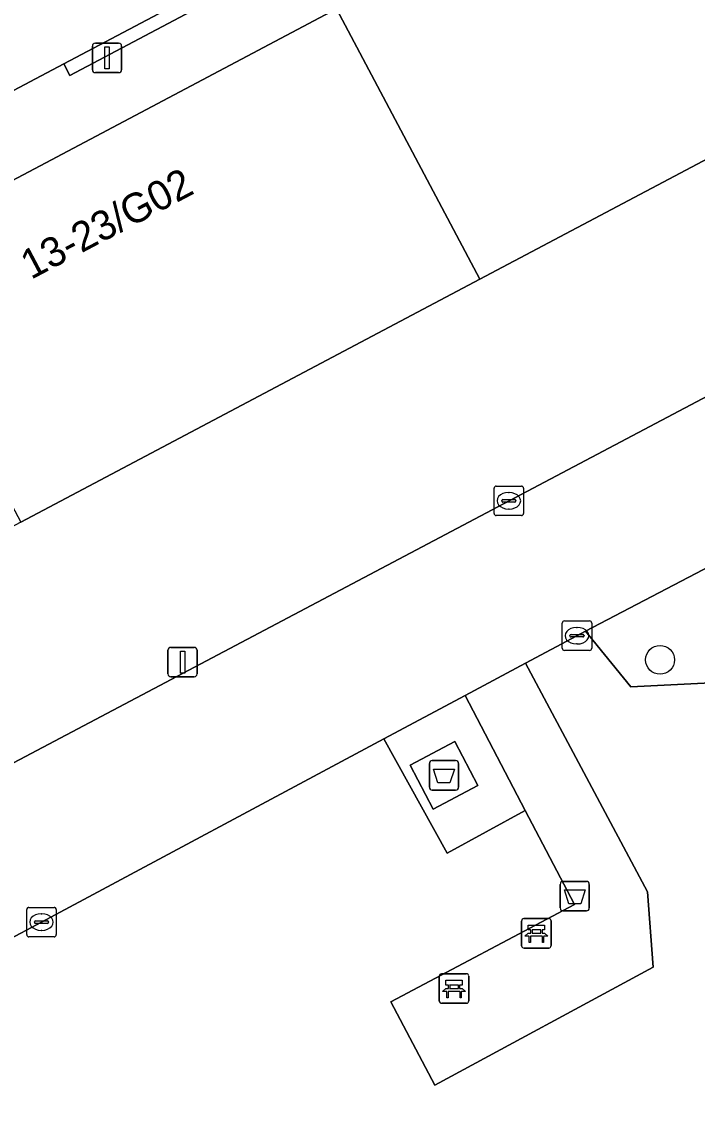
# Model space of a CAD drawing. Extents: x 159674 to 160531, y 382172 to 382904.
# Drawn here: x 160052.01 to 160074.9, y 382265.94 to 382302.84 of the extents above; entities that cross this region are included whole.
import ezdxf

# ---------------------------------------------------------------- set-up
doc = ezdxf.new("R2010")
doc.units = 0
for name, color, linetype in [('IMGEO_Afval_apart_plaats', 7, 'Continuous'), ('IMGEO_Afvalbak', 7, 'Continuous'), ('IMGEO_Bank', 7, 'Continuous'), ('IMGEO_Boom', 7, 'Continuous'), ('IMGEO_Erf', 7, 'Continuous'), ('IMGEO_Groenvoorziening', 7, 'Continuous'), ('IMGEO_Kolk', 7, 'Continuous'), ('IMGEO_Lichtmast', 7, 'Continuous'), ('IMGEO_Pand', 7, 'Continuous'), ('IMGEO_Pand_nummerreeks', 7, 'Continuous'), ('IMGEO_Rijbaan_lokaal_open', 7, 'Continuous'), ('IMGEO_Voetpad_gesloten', 7, 'Continuous'), ('IMGEO_Voetpad_open', 7, 'Continuous')]:
    doc.layers.add(name, color=color, linetype=linetype)

msp = doc.modelspace()

# ---------------------------------------------------------------- linework, layer by layer
at = {"layer": 'IMGEO_Afval_apart_plaats'}
for p, q in [((160065.925, 382277.79), (160066.715, 382277.79)), ((160066.715, 382277.79), (160065.925, 382277.79)), ((160065.825, 382276.89), (160065.825, 382277.69)), ((160065.825, 382277.69), (160065.825, 382276.89)), ((160066.815, 382277.69), (160066.815, 382276.89)), ((160066.815, 382276.89), (160066.815, 382277.69)), ((160066.715, 382276.79), (160065.925, 382276.79)), ((160065.925, 382276.79), (160066.715, 382276.79))]:
    msp.add_line(p, q, dxfattribs=at)
msp.add_lwpolyline([(160065.968, 382277.504), (160066.672, 382277.504), (160066.523, 382277.034), (160066.117, 382277.034), (160065.968, 382277.504)], dxfattribs=at)
for centre, start, end in [((160065.925, 382277.69), 90, 180), ((160065.925, 382277.69), 90, 180), ((160066.715, 382277.69), 0, 90), ((160066.715, 382277.69), 360, 90), ((160065.925, 382276.89), 180, 270), ((160065.925, 382276.89), 180, 270), ((160066.715, 382276.89), 270, 0), ((160066.715, 382276.89), 270, 0)]:
    msp.add_arc(centre, 0.1, start, end, dxfattribs=at)
at = {"layer": 'IMGEO_Afvalbak'}
for p, q in [((160070.357, 382273.695), (160071.147, 382273.695)), ((160071.147, 382273.695), (160070.357, 382273.695)), ((160070.257, 382272.795), (160070.257, 382273.595)), ((160070.257, 382273.595), (160070.257, 382272.795)), ((160071.247, 382273.595), (160071.247, 382272.795)), ((160071.247, 382272.795), (160071.247, 382273.595)), ((160071.147, 382272.695), (160070.357, 382272.695)), ((160070.357, 382272.695), (160071.147, 382272.695))]:
    msp.add_line(p, q, dxfattribs=at)
msp.add_lwpolyline([(160070.4, 382273.409), (160071.104, 382273.409), (160070.955, 382272.939), (160070.549, 382272.939), (160070.4, 382273.409)], dxfattribs=at)
for centre, start, end in [((160070.357, 382273.595), 90, 180), ((160070.357, 382273.595), 90, 180), ((160071.147, 382273.595), 0, 90), ((160071.147, 382273.595), 360, 90), ((160070.357, 382272.795), 180, 270), ((160070.357, 382272.795), 180, 270), ((160071.147, 382272.795), 270, 0), ((160071.147, 382272.795), 270, 0)]:
    msp.add_arc(centre, 0.1, start, end, dxfattribs=at)
at = {"layer": 'IMGEO_Bank'}
for p, q in [((160068.952, 382271.51), (160068.952, 382272.351)), ((160068.952, 382272.351), (160068.952, 382271.51)), ((160069.027, 382272.435), (160069.868, 382272.435)), ((160069.868, 382272.435), (160069.027, 382272.435)), ((160069.952, 382272.36), (160069.952, 382271.519)), ((160069.952, 382271.519), (160069.952, 382272.36)), ((160069.649, 382271.833), (160069.256, 382271.833)), ((160069.261, 382271.941), (160069.261, 382272.047)), ((160069.305, 382272.047), (160069.305, 382271.941)), ((160069.593, 382272.053), (160069.311, 382272.053)), ((160069.311, 382271.935), (160069.593, 382271.935)), ((160069.599, 382271.941), (160069.599, 382272.047)), ((160069.643, 382272.047), (160069.643, 382271.941)), ((160069.877, 382271.435), (160069.036, 382271.435)), ((160069.036, 382271.435), (160069.877, 382271.435)), ((160066.161, 382269.637), (160066.161, 382270.478)), ((160066.161, 382270.478), (160066.161, 382269.637)), ((160066.236, 382270.562), (160067.077, 382270.562)), ((160067.077, 382270.562), (160066.236, 382270.562)), ((160067.161, 382270.487), (160067.161, 382269.646)), ((160067.161, 382269.646), (160067.161, 382270.487)), ((160066.47, 382270.068), (160066.47, 382270.174)), ((160066.514, 382270.174), (160066.514, 382270.068)), ((160066.802, 382270.18), (160066.52, 382270.18)), ((160066.52, 382270.062), (160066.802, 382270.062)), ((160066.808, 382270.068), (160066.808, 382270.174)), ((160066.852, 382270.174), (160066.852, 382270.068)), ((160066.858, 382269.96), (160066.465, 382269.96)), ((160067.086, 382269.562), (160066.245, 382269.562)), ((160066.245, 382269.562), (160067.086, 382269.562))]:
    msp.add_line(p, q, dxfattribs=at)
for points in [[(160069.255, 382272.053), (160069.169, 382272.053), (160069.169, 382272.214), (160069.732, 382272.214), (160069.732, 382272.053), (160069.649, 382272.053)], [(160069.199, 382271.833), (160069.057, 382271.833), (160069.169, 382271.935), (160069.255, 382271.935)], [(160069.249, 382271.826), (160069.249, 382271.619), (160069.206, 382271.619), (160069.206, 382271.826)], [(160069.649, 382271.935), (160069.732, 382271.935), (160069.844, 382271.833), (160069.705, 382271.833)], [(160069.699, 382271.826), (160069.699, 382271.619), (160069.655, 382271.619), (160069.655, 382271.826)], [(160066.408, 382269.96), (160066.266, 382269.96), (160066.378, 382270.062), (160066.464, 382270.062)], [(160066.464, 382270.18), (160066.378, 382270.18), (160066.378, 382270.341), (160066.941, 382270.341), (160066.941, 382270.18), (160066.858, 382270.18)], [(160066.858, 382270.062), (160066.941, 382270.062), (160067.053, 382269.96), (160066.914, 382269.96)], [(160066.458, 382269.953), (160066.458, 382269.746), (160066.415, 382269.746), (160066.415, 382269.953)], [(160066.908, 382269.953), (160066.908, 382269.746), (160066.864, 382269.746), (160066.864, 382269.953)]]:
    msp.add_lwpolyline(points, dxfattribs=at)
for centre, radius, start, end in [((160069.03, 382272.357), 0.0779, 92.4484, 184.2845), ((160069.03, 382272.357), 0.0779, 92.4484, 184.2845), ((160069.874, 382272.357), 0.0779, 2.4484, 94.2845), ((160069.874, 382272.357), 0.0779, 2.4484, 94.2845), ((160069.199, 382271.826), 0.00671, 2.8957, 87.1043), ((160069.256, 382271.826), 0.00671, 92.8957, 177.1043), ((160069.254, 382272.046), 0.00671, 2.8957, 87.1043), ((160069.254, 382271.942), 0.00671, 272.8957, 357.1043), ((160069.311, 382272.046), 0.00671, 92.8957, 177.1043), ((160069.311, 382271.942), 0.00671, 182.8957, 267.1043), ((160069.593, 382272.046), 0.00671, 2.8957, 87.1043), ((160069.593, 382271.942), 0.00671, 272.8957, 357.1043), ((160069.65, 382272.046), 0.00671, 92.8957, 177.1043), ((160069.65, 382271.942), 0.00671, 182.8957, 267.1043), ((160069.648, 382271.826), 0.00671, 2.8957, 87.1043), ((160069.705, 382271.826), 0.00671, 92.8957, 177.1043), ((160069.03, 382271.513), 0.0779, 182.4484, 274.2845), ((160069.03, 382271.513), 0.0779, 182.4484, 274.2845), ((160069.874, 382271.513), 0.0779, 272.4484, 4.2845), ((160069.874, 382271.513), 0.0779, 272.4484, 4.2845), ((160066.239, 382270.484), 0.0779, 92.4484, 184.2845), ((160066.239, 382270.484), 0.0779, 92.4484, 184.2845), ((160067.083, 382270.484), 0.0779, 2.4484, 94.2845), ((160067.083, 382270.484), 0.0779, 2.4484, 94.2845), ((160066.463, 382270.173), 0.00671, 2.8957, 87.1043), ((160066.463, 382270.069), 0.00671, 272.8957, 357.1043), ((160066.52, 382270.173), 0.00671, 92.8957, 177.1043), ((160066.52, 382270.069), 0.00671, 182.8957, 267.1043), ((160066.802, 382270.173), 0.00671, 2.8957, 87.1043), ((160066.802, 382270.069), 0.00671, 272.8957, 357.1043), ((160066.859, 382270.173), 0.00671, 92.8957, 177.1043), ((160066.859, 382270.069), 0.00671, 182.8957, 267.1043), ((160066.239, 382269.64), 0.0779, 182.4484, 274.2845), ((160066.239, 382269.64), 0.0779, 182.4484, 274.2845), ((160066.408, 382269.953), 0.00671, 2.8957, 87.1043), ((160066.465, 382269.953), 0.00671, 92.8957, 177.1043), ((160066.857, 382269.953), 0.00671, 2.8957, 87.1043), ((160066.914, 382269.953), 0.00671, 92.8957, 177.1043), ((160067.083, 382269.64), 0.0779, 272.4484, 4.2845), ((160067.083, 382269.64), 0.0779, 272.4484, 4.2845)]:
    msp.add_arc(centre, radius, start, end, dxfattribs=at)
at = {"layer": 'IMGEO_Boom'}
msp.add_circle((160073.644, 382281.208), 0.489, dxfattribs=at)
at = {"layer": 'IMGEO_Erf'}
for points in [[(160086.028, 382319.631), (160083.339, 382319.397), (160078.204, 382311.499), (160083.057, 382302.331), (160067.532, 382294.112), (160051.977, 382285.878), (160036.422, 382277.643), (160020.867, 382269.409), (160016.014, 382278.577), (160005.765, 382273.145), (160019.447, 382262.957), (160024.762, 382259.009)], [(160034.319, 382268.512), (160078.039, 382291.633)]]:
    msp.add_lwpolyline(points, dxfattribs=at)
at = {"layer": 'IMGEO_Groenvoorziening'}
for points in [[(160079.096, 382286.347), (160071.119, 382282.18), (160072.654, 382280.295), (160075.37, 382280.425), (160104.517, 382274.01), (160105.327, 382275.04), (160090.303, 382285.839)], [(160067.688, 382235.292), (160105.142, 382241.788), (160106.23, 382250), (160109.176, 382272.273), (160105.327, 382275.04), (160104.517, 382274.01), (160075.37, 382280.425), (160072.654, 382280.295), (160071.119, 382282.18), (160070.827, 382282.027), (160069.084, 382281.094), (160073.22, 382273.339), (160073.408, 382270.787), (160066.015, 382266.781), (160064.524, 382269.606), (160070.744, 382272.909), (160069.073, 382276.104), (160066.433, 382274.656), (160064.282, 382278.525), (160052.678, 382272.316), (160035.422, 382263.138)]]:
    msp.add_lwpolyline(points, dxfattribs=at)
at = {"layer": 'IMGEO_Kolk'}
for p, q in [((160068.018, 382286.174), (160068.018, 382287.026)), ((160068.093, 382287.1), (160068.945, 382287.1)), ((160069.019, 382287.026), (160069.019, 382286.174)), ((160068.277, 382286.594), (160068.277, 382286.606)), ((160068.32, 382286.643), (160068.718, 382286.643)), ((160068.506, 382286.88), (160068.531, 382286.88)), ((160068.761, 382286.606), (160068.761, 382286.594)), ((160068.715, 382286.557), (160068.317, 382286.557)), ((160068.529, 382286.32), (160068.504, 382286.32)), ((160068.945, 382286.1), (160068.093, 382286.1)), ((160070.402, 382282.526), (160071.254, 382282.526)), ((160070.327, 382281.6), (160070.327, 382282.452)), ((160070.815, 382282.306), (160070.84, 382282.306)), ((160071.328, 382282.452), (160071.328, 382281.6)), ((160070.586, 382282.02), (160070.586, 382282.032)), ((160071.024, 382281.983), (160070.626, 382281.983)), ((160070.629, 382282.069), (160071.027, 382282.069)), ((160071.07, 382282.032), (160071.07, 382282.02)), ((160071.254, 382281.526), (160070.402, 382281.526)), ((160070.838, 382281.746), (160070.813, 382281.746)), ((160052.178, 382271.889), (160052.178, 382272.741)), ((160052.253, 382272.815), (160053.105, 382272.815)), ((160052.666, 382272.595), (160052.691, 382272.595)), ((160053.179, 382272.741), (160053.179, 382271.889)), ((160052.437, 382272.309), (160052.437, 382272.321)), ((160052.875, 382272.272), (160052.477, 382272.272)), ((160052.48, 382272.358), (160052.878, 382272.358)), ((160052.921, 382272.321), (160052.921, 382272.309)), ((160052.689, 382272.035), (160052.664, 382272.035)), ((160053.105, 382271.815), (160052.253, 382271.815))]:
    msp.add_line(p, q, dxfattribs=at)
for points in [[(160068.018, 382286.174), (160068.018, 382287.026)], [(160068.093, 382287.1), (160068.945, 382287.1)], [(160069.019, 382287.026), (160069.019, 382286.174)], [(160068.945, 382286.1), (160068.093, 382286.1)], [(160070.402, 382282.526), (160071.254, 382282.526)], [(160070.327, 382281.6), (160070.327, 382282.452)], [(160071.328, 382282.452), (160071.328, 382281.6)], [(160071.254, 382281.526), (160070.402, 382281.526)], [(160052.178, 382271.889), (160052.178, 382272.741)], [(160052.253, 382272.815), (160053.105, 382272.815)], [(160053.179, 382272.741), (160053.179, 382271.889)], [(160053.105, 382271.815), (160052.253, 382271.815)]]:
    msp.add_lwpolyline(points, dxfattribs=at)
for centre, radius, start, end in [((160068.095, 382287.024), 0.0765, 91.552, 178.448), ((160068.095, 382287.024), 0.0765, 91.552, 178.448), ((160068.943, 382287.024), 0.0765, 1.552, 88.448), ((160068.943, 382287.024), 0.0765, 1.552, 88.448), ((160068.317, 382286.603), 0.0403, 85.8775, 175.7526), ((160068.314, 382286.593), 0.0366, 178.938, 274.7102), ((160068.718, 382286.6), 0.043, 264.8664, 352.4533), ((160068.722, 382286.605), 0.0386, 1.7309, 96.639), ((160068.095, 382286.176), 0.0765, 181.552, 268.448), ((160068.095, 382286.176), 0.0765, 181.552, 268.448), ((160068.943, 382286.176), 0.0765, 271.552, 358.448), ((160068.943, 382286.176), 0.0765, 271.552, 358.448), ((160070.404, 382282.45), 0.0765, 91.552, 178.448), ((160070.404, 382282.45), 0.0765, 91.552, 178.448), ((160071.252, 382282.45), 0.0765, 1.552, 88.448), ((160071.252, 382282.45), 0.0765, 1.552, 88.448), ((160070.626, 382282.029), 0.0403, 85.8775, 175.7526), ((160070.623, 382282.019), 0.0366, 178.938, 274.7102), ((160071.027, 382282.026), 0.043, 264.8664, 352.4533), ((160071.031, 382282.031), 0.0386, 1.7309, 96.639), ((160070.404, 382281.602), 0.0765, 181.552, 268.448), ((160070.404, 382281.602), 0.0765, 181.552, 268.448), ((160071.252, 382281.602), 0.0765, 271.552, 358.448), ((160071.252, 382281.602), 0.0765, 271.552, 358.448), ((160052.255, 382272.739), 0.0765, 91.552, 178.448), ((160052.255, 382272.739), 0.0765, 91.552, 178.448), ((160053.103, 382272.739), 0.0765, 1.552, 88.448), ((160053.103, 382272.739), 0.0765, 1.552, 88.448), ((160052.477, 382272.318), 0.0403, 85.8775, 175.7526), ((160052.474, 382272.308), 0.0366, 178.938, 274.7102), ((160052.878, 382272.315), 0.043, 264.8664, 352.4533), ((160052.882, 382272.32), 0.0386, 1.7309, 96.639), ((160052.255, 382271.891), 0.0765, 181.552, 268.448), ((160052.255, 382271.891), 0.0765, 181.552, 268.448), ((160053.103, 382271.891), 0.0765, 271.552, 358.448), ((160053.103, 382271.891), 0.0765, 271.552, 358.448)]:
    msp.add_arc(centre, radius, start, end, dxfattribs=at)
for centre, major_axis, ratio, start_param, end_param in [((160068.505, 382286.6), (-0.387, 0.002), 0.722429, 4.712389, 7.853982), ((160068.53, 382286.6), (-0.39, 0.002), 0.717154, 1.570796, 4.712389), ((160070.814, 382282.026), (-0.387, 0.002), 0.722429, 4.712389, 7.853982), ((160070.839, 382282.026), (-0.39, 0.002), 0.717154, 1.570796, 4.712389), ((160052.665, 382272.315), (-0.387, 0.002), 0.722429, 4.712389, 7.853982), ((160052.69, 382272.315), (-0.39, 0.002), 0.717154, 1.570796, 4.712389)]:
    msp.add_ellipse(centre, major_axis=major_axis, ratio=ratio, start_param=start_param, end_param=end_param, dxfattribs=at)
at = {"layer": 'IMGEO_Lichtmast'}
for p, q in [((160054.504, 382302.117), (160055.294, 382302.117)), ((160055.294, 382302.117), (160054.504, 382302.117)), ((160054.404, 382301.217), (160054.404, 382302.017)), ((160054.404, 382302.017), (160054.404, 382301.217)), ((160055.394, 382302.017), (160055.394, 382301.217)), ((160055.394, 382301.217), (160055.394, 382302.017)), ((160055.294, 382301.117), (160054.504, 382301.117)), ((160054.504, 382301.117), (160055.294, 382301.117)), ((160056.965, 382280.731), (160056.965, 382281.531)), ((160056.965, 382281.531), (160056.965, 382280.731)), ((160057.065, 382281.631), (160057.855, 382281.631)), ((160057.855, 382281.631), (160057.065, 382281.631)), ((160057.955, 382281.531), (160057.955, 382280.731)), ((160057.955, 382280.731), (160057.955, 382281.531)), ((160057.855, 382280.631), (160057.065, 382280.631)), ((160057.065, 382280.631), (160057.855, 382280.631))]:
    msp.add_line(p, q, dxfattribs=at)
for points in [[(160054.824, 382301.992), (160054.974, 382301.992), (160054.974, 382301.242), (160054.824, 382301.242), (160054.824, 382301.992)], [(160057.385, 382281.506), (160057.535, 382281.506), (160057.535, 382280.756), (160057.385, 382280.756), (160057.385, 382281.506)]]:
    msp.add_lwpolyline(points, dxfattribs=at)
for centre, start, end in [((160054.504, 382302.017), 90, 180), ((160054.504, 382302.017), 90, 180), ((160055.294, 382302.017), 0, 90), ((160055.294, 382302.017), 360, 90), ((160054.504, 382301.217), 180, 270), ((160054.504, 382301.217), 180, 270), ((160055.294, 382301.217), 270, 0), ((160055.294, 382301.217), 270, 0), ((160057.065, 382281.531), 90, 180), ((160057.065, 382281.531), 90, 180), ((160057.855, 382281.531), 0, 90), ((160057.855, 382281.531), 360, 90), ((160057.065, 382280.731), 180, 270), ((160057.065, 382280.731), 180, 270), ((160057.855, 382280.731), 270, 0), ((160057.855, 382280.731), 270, 0)]:
    msp.add_arc(centre, 0.1, start, end, dxfattribs=at)
at = {"layer": 'IMGEO_Pand'}
for points in [[(160062.679, 382303.28), (160067.532, 382294.112), (160083.057, 382302.331), (160078.204, 382311.499)], [(160062.679, 382303.28), (160047.124, 382295.046), (160051.977, 382285.878), (160067.532, 382294.112)]]:
    msp.add_lwpolyline(points, close=True, dxfattribs=at)
at = {"layer": 'IMGEO_Rijbaan_lokaal_open'}
for points in [[(160038.601, 382293.559), (160053.435, 382301.412), (160065.313, 382307.7)], [(160078.039, 382291.633), (160034.319, 382268.512)], [(160064.282, 382278.525), (160067.036, 382279.998), (160069.084, 382281.094), (160070.827, 382282.027), (160071.119, 382282.18), (160079.096, 382286.347)], [(160035.422, 382263.138), (160052.678, 382272.316), (160064.282, 382278.525)]]:
    msp.add_lwpolyline(points, dxfattribs=at)
at = {"layer": 'IMGEO_Voetpad_gesloten'}
msp.add_lwpolyline([(160066.684, 382278.435), (160065.171, 382277.639), (160065.957, 382276.145), (160067.47, 382276.941)], close=True, dxfattribs=at)
at = {"layer": 'IMGEO_Voetpad_open'}
for points in [[(160070.385, 382311.081), (160070.878, 382310.15), (160053.641, 382301.024), (160053.435, 382301.412), (160038.601, 382293.559), (160038.806, 382293.171), (160020.946, 382283.715), (160020.74, 382284.104), (160014.527, 382280.815), (160003.473, 382274.856), (160005.765, 382273.145), (160016.014, 382278.577), (160031.569, 382286.811), (160047.124, 382295.046), (160062.679, 382303.28)], [(160065.313, 382307.7), (160053.435, 382301.412), (160053.641, 382301.024), (160070.878, 382310.15), (160070.385, 382311.081)]]:
    msp.add_lwpolyline(points, dxfattribs=at)
for points in [[(160069.084, 382281.094), (160067.036, 382279.998), (160069.073, 382276.104), (160070.744, 382272.909), (160064.524, 382269.606), (160066.015, 382266.781), (160073.408, 382270.787), (160073.22, 382273.339)], [(160067.036, 382279.998), (160064.282, 382278.525), (160066.433, 382274.656), (160069.073, 382276.104)], [(160065.957, 382276.145), (160065.171, 382277.639), (160066.684, 382278.435), (160067.47, 382276.941)]]:
    msp.add_lwpolyline(points, close=True, dxfattribs=at)

# ---------------------------------------------------------------- texts
at = {"layer": 'IMGEO_Pand_nummerreeks'}
msp.add_text('13-23/G02', height=1, rotation=27.8957, dxfattribs=at).set_placement((160052.322, 382294.086))

doc.saveas('drawing.dxf')
